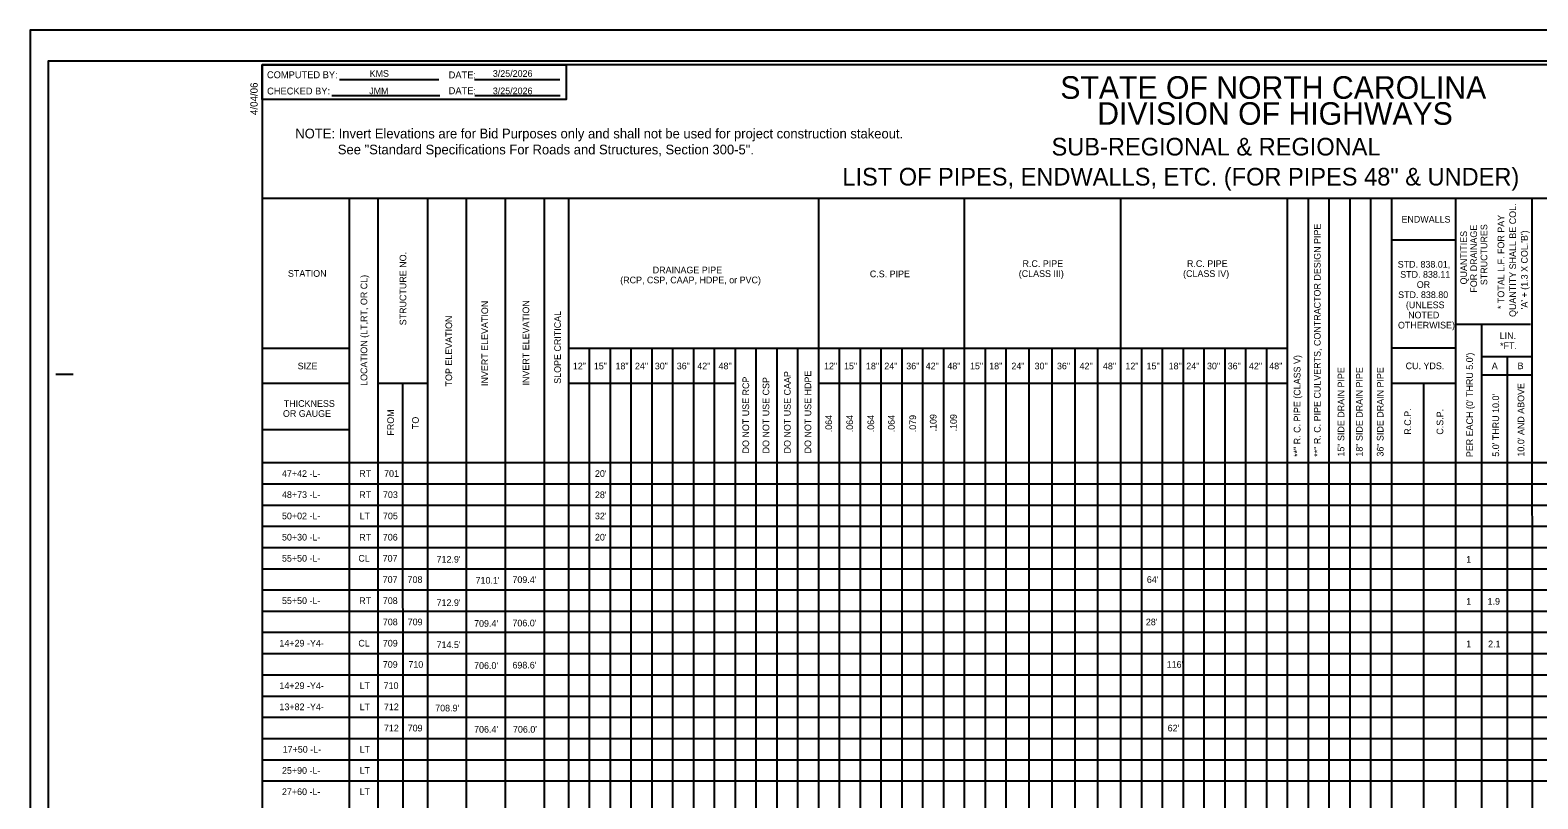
# Model space of a CAD drawing. Extents: x 1912419 to 1914138, y 231793 to 234289.
# Drawn here: x 1912419 to 1913505, y 232339 to 232893 of the extents above; entities that cross this region are included whole.
import ezdxf

# ---------------------------------------------------------------- set-up
doc = ezdxf.new("R2010")
doc.units = 0
for name, color, linetype in [('Sheet Cutting Line CELL', 7, 'Continuous'), ('Sheet Pipe Summary CELL', 7, 'Continuous'), ('Sheet Pipe Summary Grid CELL', 7, 'Continuous'), ('Sheet Plot Border Inside CELL', 7, 'Continuous'), ('Sheet Plot Border Outside CELL', 7, 'Continuous'), ('Sheet Summary Combination CELL', 7, 'Continuous')]:
    doc.layers.add(name, color=color, linetype=linetype)

msp = doc.modelspace()

# ---------------------------------------------------------------- linework, layer by layer
at = {"layer": 'Sheet Cutting Line CELL'}
for p, q in [((1914103.4, 232892.5), (1912419.4, 232892.5)), ((1912419.4, 232892.5), (1912419.4, 231792.5))]:
    msp.add_line(p, q, dxfattribs=at)
at = {"layer": 'Sheet Pipe Summary CELL'}
for p, q in [((1912642.1, 232857.1), (1912713.6, 232857.1)), ((1912739.4, 232857), (1912800.8, 232857)), ((1912636.6, 232845.4), (1912714.3, 232845.4)), ((1912739.6, 232845.5), (1912801, 232845.5)), ((1912437.9, 232645), (1912450.4, 232645)), ((1912437.9, 232645), (1912450.4, 232645))]:
    msp.add_line(p, q, dxfattribs=at)
for points in [[(1914086.4, 232867.5), (1912586.4, 232867.5), (1912586.4, 231817.5), (1914086.4, 231817.5)], [(1912586.4, 232867.5), (1912805.4, 232867.5), (1912805.4, 232842.5), (1912586.4, 232842.5)]]:
    msp.add_lwpolyline(points, close=True, dxfattribs=at)
at = {"layer": 'Sheet Pipe Summary Grid CELL'}
for p, q in [((1914086.4, 232771.4), (1912586.4, 232771.3)), ((1912649.4, 231817.5), (1912649.4, 232771.3)), ((1912670, 231817.5), (1912669.9, 232771.3)), ((1912705.7, 231817.5), (1912705.7, 232771.3)), ((1912733.7, 231817.5), (1912733.6, 232771.3)), ((1912761.7, 231817.5), (1912761.6, 232771.3)), ((1912789.6, 231817.5), (1912789.6, 232771.3)), ((1912807.1, 231817.5), (1912807.1, 232771.3)), ((1912987.1, 231817.5), (1912987.1, 232771.3)), ((1913092.1, 231817.5), (1913092.1, 232771.3)), ((1913204.7, 231817.6), (1913204.6, 232771.4)), ((1913324.7, 231817.6), (1913324.6, 232771.4)), ((1913339.7, 231817.6), (1913339.6, 232771.4)), ((1913354.7, 231817.6), (1913354.6, 232771.4)), ((1913354.7, 231817.6), (1913354.6, 232771.4)), ((1913369.7, 231817.6), (1913369.6, 232771.4)), ((1913384.7, 231817.6), (1913384.6, 232771.4)), ((1913399.6, 231817.6), (1913399.6, 232771.4)), ((1913445.9, 231817.6), (1913445.8, 232771.4)), ((1913500.9, 231817.6), (1913500.8, 232771.4)), ((1913500.9, 231817.6), (1913500.8, 232771.4)), ((1913445.8, 232741.4), (1913399.6, 232741.4)), ((1913499.6, 232680.7), (1913445.9, 232680.7)), ((1913464.5, 231817.6), (1913464.4, 232680.7)), ((1912649.4, 232663.5), (1912586.4, 232663.5)), ((1913324.6, 232663.5), (1912807.1, 232663.5)), ((1912822.1, 231817.5), (1912822.1, 232663.5)), ((1912837.1, 231817.5), (1912837.1, 232663.5)), ((1912852.1, 231817.5), (1912852.1, 232663.5)), ((1912867.1, 231817.5), (1912867.1, 232663.5)), ((1912882.1, 231817.5), (1912882.1, 232663.5)), ((1912897.1, 231817.5), (1912897.1, 232663.5)), ((1912912.1, 231817.5), (1912912.1, 232663.5)), ((1912927.1, 231817.5), (1912927.1, 232663.5)), ((1912942.1, 231817.5), (1912942.1, 232663.5)), ((1912957.1, 231817.5), (1912957.1, 232663.5)), ((1912972.1, 231817.5), (1912972.1, 232663.5)), ((1913002.1, 231817.5), (1913002.1, 232663.5)), ((1913017.1, 231817.5), (1913017.1, 232663.5)), ((1913032.1, 231817.5), (1913032.1, 232663.5)), ((1913047.1, 231817.5), (1913047.1, 232663.5)), ((1913062.1, 231817.5), (1913062.1, 232663.5)), ((1913077.1, 231817.5), (1913077.1, 232663.5)), ((1913092.1, 231817.5), (1913092.1, 232663.5)), ((1913107.1, 231817.5), (1913107.1, 232663.5)), ((1913122.1, 231817.5), (1913122.1, 232663.5)), ((1913138.6, 231817.5), (1913138.6, 232663.5)), ((1913155.1, 231817.5), (1913155.1, 232663.5)), ((1913171.6, 231817.5), (1913171.6, 232663.5)), ((1913188.1, 231817.5), (1913188.1, 232663.5)), ((1913204.6, 231817.5), (1913204.6, 232663.5)), ((1913219.6, 231817.5), (1913219.6, 232663.5)), ((1913234.6, 231817.5), (1913234.6, 232663.5)), ((1913249.6, 231817.5), (1913249.6, 232663.5)), ((1913264.6, 231817.5), (1913264.6, 232663.5)), ((1913279.6, 231817.5), (1913279.6, 232663.5)), ((1913294.6, 231817.5), (1913294.6, 232663.5)), ((1913309.6, 231817.5), (1913309.6, 232663.5)), ((1913324.6, 231817.5), (1913324.6, 232663.5)), ((1913445.8, 232663.6), (1913399.6, 232663.6)), ((1913500.8, 232657.5), (1913464.4, 232657.5)), ((1913483.1, 231817.6), (1913483, 232657.5)), ((1912649.4, 232638.1), (1912586.4, 232638.1)), ((1912705.7, 232638.1), (1912669.9, 232638.1)), ((1912687.9, 231817.5), (1912687.8, 232638.1)), ((1912927.1, 232638.1), (1912807.1, 232638.1)), ((1912987.1, 231817.5), (1912987.1, 232638.1)), ((1913324.6, 232638.1), (1912987.1, 232638.1)), ((1913445.8, 232638.2), (1913399.6, 232638.2)), ((1913422.8, 231817.6), (1913422.7, 232638.2)), ((1913500.8, 232644.3), (1913464.4, 232644.3)), ((1912649.4, 232604.9), (1912586.4, 232604.9)), ((1914086.4, 232581), (1912586.4, 232581)), ((1914086.4, 232565.7), (1912586.4, 232565.7)), ((1914086.4, 232550.5), (1912586.4, 232550.5)), ((1914086.4, 232535.2), (1912586.4, 232535.2)), ((1914086.4, 232519.9), (1912586.4, 232519.9)), ((1914086.4, 232504.7), (1912586.4, 232504.7)), ((1914086.4, 232489.4), (1912586.4, 232489.4)), ((1914086.4, 232474.1), (1912586.4, 232474.1)), ((1914086.4, 232458.9), (1912586.4, 232458.9)), ((1914086.4, 232443.6), (1912586.4, 232443.6)), ((1914086.4, 232428.3), (1912586.4, 232428.3)), ((1914086.4, 232413), (1912586.4, 232413)), ((1914086.4, 232397.8), (1912586.4, 232397.8)), ((1914086.4, 232382.5), (1912586.4, 232382.5)), ((1914086.4, 232367.2), (1912586.4, 232367.2)), ((1914086.4, 232352), (1912586.4, 232352))]:
    msp.add_line(p, q, dxfattribs=at)
at = {"layer": 'Sheet Plot Border Inside CELL'}
msp.add_lwpolyline([(1912432.4, 231815), (1914098.9, 231815), (1914098.9, 232870.1), (1912432.4, 232870.1)], close=True, dxfattribs=at)
at = {"layer": 'Sheet Plot Border Outside CELL'}
msp.add_lwpolyline([(1912419.4, 231792.5), (1914103.4, 231792.5), (1914103.4, 232892.5), (1912419.4, 232892.5)], close=True, dxfattribs=at)

# ---------------------------------------------------------------- texts
at = {"layer": 'Sheet Pipe Summary CELL'}
for s, height, rotation, p in [('4/04/06', 5.25, 90, (1912583.2, 232831.4)), ('QUANTITY SHALL BE COL.', 4.8, 90, (1913489.1, 232686.1)), ('* TOTAL L.F. FOR PAY', 4.8, 90, (1913480.6, 232691.8)), ('**" R. C. PIPE CULVERTS, CONTRACTOR DESIGN PIPE', 4.8, 90, (1913348.4, 232585.5)), ('QUANTITIES', 4.8, 90, (1913453.8, 232709.5)), ('FOR DRAINAGE', 4.8, 90, (1913461, 232703.6)), ('STRUCTURES', 4.8, 90, (1913468.4, 232709)), ("'A' + (1.3 X COL.'B')", 4.8, 90, (1913497.5, 232691.6)), ('STRUCTURE NO.', 4.8, 90, (1912690.2, 232680.1)), ('STATION', 4.8, 360, (1912605, 232715)), ('LOCATION (LT,RT, OR CL)', 4.8, 90, (1912662.1, 232636.5)), ('INVERT ELEVATION', 4.8, 90, (1912749.1, 232636.4)), ('INVERT ELEVATION', 4.8, 90, (1912778.7, 232636.8)), ('SLOPE CRITICAL', 4.8, 90, (1912801.5, 232638)), ('TOP ELEVATION', 4.8, 90, (1912723.2, 232636.1)), ('**" R. C. PIPE (CLASS V)', 4.8, 90, (1913333.9, 232585.4)), ("PER EACH (0' THRU 5.0')", 4.799, 90.0369, (1913458.1, 232585.2)), ('DO NOT USE CAAP', 4.8, 90, (1912966.9, 232587.9)), ('DO NOT USE HDPE', 4.8, 90, (1912981.7, 232587.9)), ('15" SIDE DRAIN PIPE', 4.8, 90, (1913365.5, 232585.6)), ('18" SIDE DRAIN PIPE', 4.8, 90, (1913378.7, 232585.6)), ('36" SIDE DRAIN PIPE', 4.8, 90, (1913393.7, 232585.6)), ('DO NOT USE RCP', 4.8, 90, (1912937, 232587.9)), ('DO NOT USE CSP', 4.8, 90, (1912951.5, 232587.9)), ("10.0' AND ABOVE", 4.8, 90, (1913495, 232585.6)), ("5.0' THRU 10.0'", 4.8, 90, (1913476.9, 232585.5)), ('FROM', 4.8, 90, (1912681.3, 232600.7)), ('.064', 4.8, 90, (1912996.7, 232603.1)), ('.064', 4.8, 90, (1913011.8, 232603.1)), ('.064', 4.8, 90, (1913027, 232603.1)), ('.064', 4.8, 90, (1913041.8, 232603.1)), ('.079', 4.8, 90, (1913057.2, 232603.1)), ('.109', 4.8, 90, (1913071.9, 232603.7)), ('.109', 4.8, 90, (1913086.5, 232603.7)), ('R.C.P.', 4.8, 90, (1913413.5, 232601.4)), ('C.S.P.', 4.8, 90, (1913436.7, 232601.4)), ('TO', 4.8, 90, (1912699.2, 232605.4))]:
    msp.add_text(s, height=height, rotation=rotation, dxfattribs=at).set_placement(p)
for s, height, p in [('COMPUTED BY:', 5, (1912589.9, 232857.9)), ('DATE:', 5, (1912720.7, 232857.8)), ('STATE OF NORTH CAROLINA', 16.25, (1913161, 232843.1)), ('CHECKED BY:', 5, (1912590, 232846.2)), ('DATE:', 5, (1912720.7, 232846.4)), ('DIVISION OF HIGHWAYS', 16.25, (1913187.6, 232824.4)), ('NOTE: Invert Elevations are for Bid Purposes only and shall not be used for project construction stakeout.', 7, (1912610.3, 232814.6)), ('See "Standard Specifications For Roads and Structures, Section 300-5".', 7, (1912640.9, 232803.1)), ('SUB-REGIONAL & REGIONAL', 12.7, (1913154.7, 232802.3)), ('LIST OF PIPES, ENDWALLS, ETC. (FOR PIPES 48" & UNDER)', 12.7, (1913004.1, 232780.7)), ('ENDWALLS', 4.8, (1913406.6, 232754)), ('R.C. PIPE', 4.8, (1913133.8, 232722.1)), ('R.C. PIPE', 4.8, (1913252.2, 232722.1)), ('STD. 838.01,', 4.8, (1913403.9, 232721.6)), ('(RCP, CSP, CAAP, HDPE, or PVC)', 4.8, (1912844.2, 232710.3)), ('DRAINAGE PIPE', 4.8, (1912867.6, 232717.5)), ('C.S. PIPE', 4.8, (1913023.9, 232714.7)), ('(CLASS III)', 4.8, (1913131.1, 232714.9)), ('(CLASS IV)', 4.8, (1913249.4, 232714.9)), ('STD. 838.11', 4.8, (1913405.7, 232714.3)), ('OR', 4.8, (1913417.6, 232707)), ('STD. 838.80', 4.8, (1913404.2, 232699.7)), ('(UNLESS', 4.8, (1913409.8, 232692.4)), ('OTHERWISE)', 4.8, (1913404.1, 232677.8)), ('NOTED', 4.8, (1913411.4, 232685.1)), ('LIN.', 4.8, (1913477.3, 232670.3)), ('*FT.', 4.8, (1913477.6, 232663)), ('SIZE', 4.8, (1912612, 232648.4)), ('12"', 4.8, (1912810.1, 232648.4)), ('15"', 4.8, (1912825.2, 232648.4)), ('18"', 4.8, (1912840.8, 232648.4)), ('24"', 4.8, (1912854.8, 232648.4)), ('30"', 4.8, (1912869.1, 232648.4)), ('36"', 4.8, (1912884.9, 232648.4)), ('42"', 4.8, (1912899.7, 232648.4)), ('48"', 4.8, (1912915, 232648.4)), ('12"', 4.8, (1912990.9, 232648.4)), ('15"', 4.8, (1913005.3, 232648.4)), ('18"', 4.8, (1913021.1, 232648.4)), ('24"', 4.8, (1913034.3, 232648.4)), ('36"', 4.8, (1913050.1, 232648.4)), ('42"', 4.8, (1913064.1, 232648.4)), ('48"', 4.8, (1913079.7, 232648.4)), ('15"', 4.8, (1913096, 232648.4)), ('18"', 4.8, (1913109.8, 232648.4)), ('24"', 4.8, (1913125.8, 232648.4)), ('30"', 4.8, (1913142.5, 232648.4)), ('36"', 4.8, (1913158.6, 232648.4)), ('42"', 4.8, (1913174.9, 232648.4)), ('48"', 4.8, (1913191.7, 232648.4)), ('12"', 4.8, (1913207.9, 232648.4)), ('15"', 4.8, (1913223.1, 232648.4)), ('18"', 4.8, (1913239, 232648.4)), ('24"', 4.8, (1913251.7, 232648.4)), ('30"', 4.8, (1913266.6, 232648.4)), ('36"', 4.8, (1913281.5, 232648.4)), ('42"', 4.8, (1913296.8, 232648.4)), ('48"', 4.8, (1913311.4, 232648.4)), ('CU. YDS.', 4.8, (1913409.6, 232648.5)), ('A', 4.8, (1913471.6, 232648.5)), ('B', 4.8, (1913490.2, 232648.5)), ('THICKNESS', 4.8, (1912602, 232621.4)), ('OR GAUGE', 4.8, (1912601.4, 232614.2))]:
    msp.add_text(s, height=height, dxfattribs=at).set_placement(p)
at = {"layer": 'Sheet Summary Combination CELL'}
for s, p in [('KMS', (1912663.8, 232858.9)), ('3/25/2026', (1912752.5, 232858.9)), ('JMM', (1912663.5, 232846.4)), ('3/25/2026', (1912752.5, 232846.4)), ('47+42 -L-', (1912600.7, 232571)), ('RT', (1912656.3, 232571)), ('701', (1912674.2, 232571)), ("20'", (1912826, 232571)), ('48+73 -L-', (1912600.7, 232555.8)), ('RT', (1912656.3, 232555.8)), ('703', (1912673.4, 232555.8)), ("28'", (1912826, 232555.7)), ('50+02 -L-', (1912600.7, 232540.5)), ('LT', (1912656.6, 232540.5)), ('705', (1912673.4, 232540.5)), ("32'", (1912826, 232540.5)), ('50+30 -L-', (1912600.7, 232525.2)), ('RT', (1912656.3, 232525.2)), ('706', (1912673.3, 232525.2)), ("20'", (1912826, 232525.2)), ('55+50 -L-', (1912600.7, 232510)), ('CL', (1912655.7, 232510)), ('707', (1912673.2, 232510)), ("712.9'", (1912712, 232509.3)), ('1', (1913453.2, 232509.2)), ('707', (1912673.2, 232494.7)), ('708', (1912691.1, 232494.7)), ("710.1'", (1912740.1, 232494.2)), ("709.4'", (1912766.6, 232494.6)), ("64'", (1913223.3, 232494.7)), ('55+50 -L-', (1912600.7, 232479.5)), ('RT', (1912656.3, 232479.5)), ('708', (1912673.3, 232479.5)), ('1.9', (1913468.6, 232479)), ("712.9'", (1912712, 232478.1)), ('1', (1913453.2, 232479)), ('708', (1912673.3, 232464.2)), ('709', (1912691.2, 232464.2)), ("709.4'", (1912739, 232463.1)), ("706.0'", (1912766.6, 232463.4)), ("28'", (1913222.6, 232464.2)), ('14+29 -Y4-', (1912598.9, 232448.9)), ('CL', (1912655.7, 232448.9)), ('709', (1912673.3, 232448.9)), ("714.5'", (1912712, 232447.8)), ('1', (1913453.2, 232448.4)), ('2.1', (1913469, 232448.4)), ('709', (1912673.3, 232433.6)), ('710', (1912691.7, 232433.6)), ("706.0'", (1912739, 232432.8)), ("698.6'", (1912766.6, 232433.1)), ("116'", (1913237.6, 232433.6)), ('14+29 -Y4-', (1912598.9, 232418.3)), ('LT', (1912656.6, 232418.4)), ('710', (1912673.9, 232418.4)), ('13+82 -Y4-', (1912598.9, 232403.1)), ('LT', (1912656.6, 232403.1)), ('712', (1912674.1, 232403.1)), ("708.9'", (1912711, 232402.2)), ('712', (1912674.1, 232387.8)), ('709', (1912691.2, 232387.8)), ("706.4'", (1912739, 232386.9)), ("706.0'", (1912767, 232386.9)), ("62'", (1913238.3, 232387.8)), ('17+50 -L-', (1912601.2, 232372.5)), ('LT', (1912656.6, 232372.5)), ('25+90 -L-', (1912600.7, 232357.3)), ('LT', (1912656.6, 232357.3)), ('27+60 -L-', (1912600.7, 232342)), ('LT', (1912656.6, 232342))]:
    msp.add_text(s, height=4.8, dxfattribs=at).set_placement(p)

doc.saveas('drawing.dxf')
